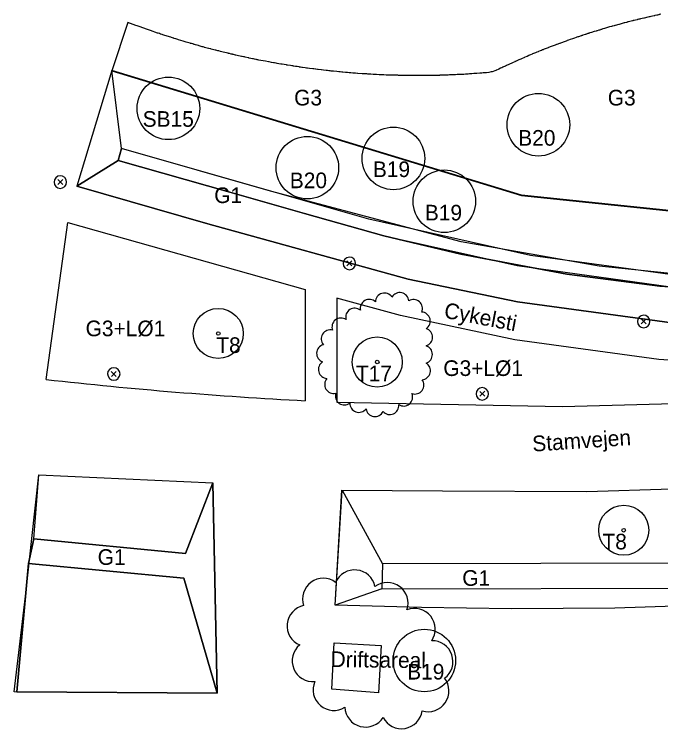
# Model space of a CAD drawing. Extents: x 0 to 512122, y 0 to 6212554.
# Drawn here: x 511513.3 to 511565, y 6211750.2 to 6211807.3 of the extents above; entities that cross this region are included whole.
import ezdxf

# ---------------------------------------------------------------- set-up
doc = ezdxf.new("R2010")
doc.units = 0
for name, color, linetype in [('_lights', 7, 'Continuous'), ('_LØ1', 7, 'Continuous'), ('Clouds', 7, 'Continuous'), ('L40 jord udlagt muld og grøft', 7, 'Continuous'), ('Pumpstation', 7, 'Continuous'), ('Skel', 7, 'Continuous'), ('TV_U_AFM_Symbl_Gul', 7, 'Continuous'), ('TV_U_LYS_Mastenummer', 7, 'Continuous')]:
    doc.layers.add(name, color=color, linetype=linetype)

# ---------------------------------------------------------------- blocks, each defined once
blk = doc.blocks.new('SOLITAIRE TREES')
at = {"layer": 'Skel'}
for radius in [2, 0.141]:
    blk.add_circle((0, 0), radius, dxfattribs=at)

msp = doc.modelspace()

# ---------------------------------------------------------------- linework, layer by layer
at = {"layer": '_lights'}
for p, q in [((511516.778, 6211794.103), (511517.172, 6211793.709)), ((511517.176, 6211794.107), (511516.782, 6211793.713)), ((511539.88, 6211787.6), (511540.274, 6211787.206)), ((511540.278, 6211787.604), (511539.884, 6211787.21)), ((511563.4, 6211782.962), (511563.795, 6211782.568)), ((511563.798, 6211782.966), (511563.404, 6211782.572)), ((511521.053, 6211778.766), (511521.447, 6211778.372)), ((511521.451, 6211778.77), (511521.057, 6211778.376)), ((511550.501, 6211777.177), (511550.895, 6211776.783)), ((511550.899, 6211777.181), (511550.505, 6211776.787))]:
    msp.add_line(p, q, dxfattribs=at)
for centre, start, end in [((511516.975, 6211793.906), 315.5636, 315), ((511516.975, 6211793.906), 315, 315.5636), ((511540.077, 6211787.403), 315.5636, 315), ((511540.077, 6211787.403), 315, 315.5636), ((511563.597, 6211782.765), 315.5636, 315), ((511563.597, 6211782.765), 315, 315.5636), ((511521.25, 6211778.569), 315.5636, 315), ((511521.25, 6211778.569), 315, 315.5636), ((511550.698, 6211776.98), 315.5636, 315), ((511550.698, 6211776.98), 315, 315.5636)]:
    msp.add_arc(centre, 0.5, start, end, dxfattribs=at)
at = {"layer": '_LØ1'}
msp.add_line((511515.849, 6211778.128), (511517.576, 6211790.672), dxfattribs=at)
msp.add_lwpolyline([(511517.576, 6211790.672), (511536.556, 6211785.33), (511536.556, 6211776.428)], dxfattribs=at)
msp.add_lwpolyline([(511539.066, 6211784.628), (511539.066, 6211776.31), (511557.102, 6211775.97), (511569.966, 6211776.326), (511576.1, 6211777.084), (511580.076, 6211777.733), (511581.646, 6211778.064), (511583.922, 6211778.583), (511584.736, 6211778.794), (511585.399, 6211778.957), (511578.113, 6211778.822), (511564.816, 6211779.711), (511553.308, 6211781.287), (511544.168, 6211783.234)], close=True, dxfattribs=at)
msp.add_arc((511554.612, 6212123.208), 347.25, 263.59085, 267.0195, dxfattribs=at)
at = {"layer": 'Clouds'}
for centre, radius, start, end in [((511542.881, 6211784.313), 0.72, 33.459, 178.459), ((511544.106, 6211784.352), 0.72, 5.2147, 150.2147), ((511541.668, 6211783.808), 0.72, 46.7383, 191.7383), ((511545.198, 6211783.803), 0.72, 336.3943, 121.3943), ((511540.504, 6211783.107), 0.72, 50.4047, 195.4047), ((511545.827, 6211782.796), 0.72, 302.5784, 87.5784), ((511539.405, 6211782.32), 0.72, 55.8288, 200.8288), ((511538.548, 6211781.368), 0.72, 75.1328, 220.1328), ((511545.998, 6211781.502), 0.72, 287.5, 72.5), ((511538.183, 6211780.208), 0.72, 104.9369, 249.9369), ((511545.997, 6211780.13), 0.72, 287.4096, 72.4096), ((511538.321, 6211778.924), 0.72, 122.3096, 267.3096), ((511545.84, 6211778.827), 0.72, 273.7995, 58.7995), ((511538.824, 6211777.725), 0.72, 138.2459, 283.2459), ((511545.309, 6211777.679), 0.72, 251.5756, 36.5756), ((511539.676, 6211776.81), 0.72, 162.6551, 307.6551), ((511544.415, 6211776.724), 0.72, 237.2694, 22.2694), ((511540.836, 6211776.216), 0.72, 178.0972, 323.0972), ((511543.31, 6211776.042), 0.72, 221.0491, 6.0491), ((511542.123, 6211775.89), 0.72, 188.5215, 333.5215), ((511540.499, 6211761.246), 1.658, 11.4218, 156.4218), ((511537.993, 6211760.576), 1.658, 53.5024, 198.5024), ((511543.11, 6211760.239), 1.659, 341.4203, 126.4203), ((511536.76, 6211758.427), 1.658, 101.8288, 246.8288), ((511545.279, 6211758.164), 1.659, 326.0856, 111.0856), ((511546.697, 6211755.579), 1.659, 306.4469, 91.4469), ((511537.17, 6211755.629), 1.659, 129.8492, 274.8492), ((511538.837, 6211753.328), 1.658, 156.995, 301.995), ((511546.376, 6211753.225), 1.658, 252.9674, 37.9674), ((511541.373, 6211751.996), 1.659, 182.559, 327.559), ((511544.247, 6211751.864), 1.658, 207.2264, 352.2264)]:
    msp.add_arc(centre, radius, start, end, dxfattribs=at)
at = {"layer": 'L40 jord udlagt muld og grøft'}
msp.add_line((511521.099, 6211802.832), (511518.303, 6211793.584), dxfattribs=at)
for points in [[(511564.982, 6211807.323), (511564.843, 6211807.293), (511564.828, 6211807.29), (511564.776, 6211807.279), (511564.703, 6211807.264), (511564.64, 6211807.25), (511564.485, 6211807.218), (511564.454, 6211807.211), (511564.446, 6211807.209), (511564.444, 6211807.209), (511564.167, 6211807.149), (511564.084, 6211807.13), (511564.048, 6211807.122), (511563.94, 6211807.099), (511563.923, 6211807.095), (511563.92, 6211807.094), (511563.625, 6211807.023), (511563.6, 6211807.017), (511563.49, 6211806.99), (511563.356, 6211806.958), (511563.343, 6211806.955), (511563.286, 6211806.941), (511563.259, 6211806.935), (511563.21, 6211806.923), (511563.14, 6211806.906), (511563.103, 6211806.897), (511563.083, 6211806.892), (511562.954, 6211806.861), (511562.837, 6211806.833), (511562.763, 6211806.815), (511562.75, 6211806.812), (511562.735, 6211806.808), (511562.733, 6211806.807), (511562.71, 6211806.802), (511562.502, 6211806.749), (511562.383, 6211806.719), (511562.332, 6211806.707), (511562.298, 6211806.698), (511562.269, 6211806.69), (511562.214, 6211806.675), (511562.102, 6211806.644), (511562.06, 6211806.633), (511562.046, 6211806.629), (511561.892, 6211806.587), (511561.889, 6211806.586), (511561.873, 6211806.582), (511561.872, 6211806.582), (511561.713, 6211806.538), (511561.648, 6211806.52), (511561.639, 6211806.518), (511561.61, 6211806.51), (511561.332, 6211806.435), (511561.29, 6211806.424), (511561.238, 6211806.41), (511561.087, 6211806.368), (511561.058, 6211806.36), (511561.028, 6211806.352), (511560.88, 6211806.312), (511560.863, 6211806.307), (511560.861, 6211806.307), (511560.778, 6211806.281), (511560.718, 6211806.263), (511560.466, 6211806.186), (511560.334, 6211806.147), (511560.226, 6211806.114), (511560.184, 6211806.101), (511560.155, 6211806.092), (511560.066, 6211806.065), (511560.027, 6211806.053), (511560.003, 6211806.046), (511559.891, 6211806.012), (511559.89, 6211806.012), (511559.843, 6211805.997), (511559.808, 6211805.987), (511559.651, 6211805.939), (511559.433, 6211805.873), (511559.308, 6211805.834), (511559.276, 6211805.824), (511559.268, 6211805.822), (511559.216, 6211805.805), (511559.187, 6211805.795), (511559.135, 6211805.777), (511559.021, 6211805.739), (511558.985, 6211805.727), (511558.952, 6211805.716), (511558.746, 6211805.647), (511558.743, 6211805.646), (511558.701, 6211805.632), (511558.661, 6211805.619), (511558.629, 6211805.608), (511558.605, 6211805.6), (511558.385, 6211805.526), (511558.365, 6211805.519), (511558.348, 6211805.514), (511558.259, 6211805.484), (511558.205, 6211805.466), (511558.081, 6211805.425), (511558.07, 6211805.421), (511558.058, 6211805.417), (511557.919, 6211805.37), (511557.721, 6211805.302), (511557.591, 6211805.255), (511557.485, 6211805.216), (511557.447, 6211805.203), (511557.446, 6211805.202), (511557.404, 6211805.187), (511557.155, 6211805.095), (511557.108, 6211805.078), (511556.945, 6211805.018), (511556.898, 6211805.001), (511556.868, 6211804.99), (511556.661, 6211804.914), (511556.641, 6211804.906), (511556.575, 6211804.882), (511556.512, 6211804.859), (511556.138, 6211804.718), (511556.113, 6211804.709), (511556.076, 6211804.694), (511556.002, 6211804.664), (511555.958, 6211804.647), (511555.793, 6211804.581), (511555.654, 6211804.525), (511555.605, 6211804.505), (511555.569, 6211804.491), (511555.523, 6211804.473), (511555.439, 6211804.439), (511555.315, 6211804.39), (511555.2, 6211804.344), (511555.165, 6211804.33), (511555.069, 6211804.291), (511555.054, 6211804.285), (511555.011, 6211804.268), (511554.945, 6211804.241), (511554.721, 6211804.152), (511554.688, 6211804.137), (511554.544, 6211804.075), (511554.477, 6211804.046), (511554.474, 6211804.045), (511554.431, 6211804.026), (511554.28, 6211803.961), (511554.114, 6211803.89), (511554.087, 6211803.878), (511554.069, 6211803.87), (511553.83, 6211803.766), (511553.786, 6211803.747), (511553.774, 6211803.742), (511553.701, 6211803.71), (511553.612, 6211803.672), (511553.355, 6211803.561), (511553.345, 6211803.556), (511553.311, 6211803.542), (511553.291, 6211803.533), (511553.156, 6211803.471), (511553.111, 6211803.45), (511552.813, 6211803.311), (511552.648, 6211803.234), (511552.545, 6211803.186), (511552.397, 6211803.117), (511552.343, 6211803.092), (511552.259, 6211803.053), (511552.154, 6211803.004), (511552.035, 6211802.948), (511551.979, 6211802.922), (511551.839, 6211802.857), (511551.839, 6211802.857), (511551.823, 6211802.85), (511551.814, 6211802.845), (511551.777, 6211802.831), (511551.496, 6211802.726), (511551.446, 6211802.716), (511551.419, 6211802.711), (511551.229, 6211802.674), (511551.229, 6211802.674), (511551.222, 6211802.673), (511551.041, 6211802.649), (511551.024, 6211802.647), (511550.911, 6211802.639), (511550.877, 6211802.637), (511550.839, 6211802.634), (511550.786, 6211802.63), (511550.781, 6211802.63), (511550.661, 6211802.622), (511550.601, 6211802.618), (511550.558, 6211802.615), (511550.504, 6211802.611), (511550.269, 6211802.594), (511550.161, 6211802.586), (511550.013, 6211802.576), (511549.854, 6211802.565), (511549.788, 6211802.56), (511549.728, 6211802.556), (511549.675, 6211802.553), (511549.579, 6211802.546), (511549.533, 6211802.543), (511549.466, 6211802.538), (511549.453, 6211802.537), (511549.369, 6211802.531), (511549.223, 6211802.521), (511549.112, 6211802.513), (511549.079, 6211802.511), (511549.06, 6211802.51), (511548.792, 6211802.5), (511548.789, 6211802.5), (511548.698, 6211802.496), (511548.555, 6211802.491), (511548.352, 6211802.483), (511548.245, 6211802.479), (511548.214, 6211802.478), (511548.192, 6211802.477), (511548.124, 6211802.475), (511548.084, 6211802.473), (511547.985, 6211802.469), (511547.94, 6211802.467), (511547.873, 6211802.465), (511547.821, 6211802.463), (511547.782, 6211802.461), (511547.675, 6211802.457), (511547.443, 6211802.448), (511547.312, 6211802.443), (511547.285, 6211802.442), (511547.236, 6211802.44), (511547.034, 6211802.434), (511547.004, 6211802.433), (511546.906, 6211802.431), (511546.776, 6211802.43), (511546.699, 6211802.43), (511546.645, 6211802.429), (511546.455, 6211802.428), (511546.442, 6211802.428), (511546.411, 6211802.428), (511546.375, 6211802.427), (511546.356, 6211802.427), (511546.295, 6211802.427), (511546.285, 6211802.427), (511546.006, 6211802.425), (511545.945, 6211802.425), (511545.78, 6211802.423), (511545.625, 6211802.422), (511545.564, 6211802.422), (511545.51, 6211802.422), (511545.475, 6211802.422), (511545.444, 6211802.422), (511545.366, 6211802.421), (511545.299, 6211802.42), (511544.997, 6211802.42), (511544.968, 6211802.42), (511544.783, 6211802.423), (511544.749, 6211802.424), (511544.611, 6211802.426), (511544.608, 6211802.426), (511544.515, 6211802.429), (511544.429, 6211802.431), (511544.369, 6211802.432), (511544.271, 6211802.434), (511544.053, 6211802.44), (511543.999, 6211802.442), (511543.951, 6211802.443), (511543.93, 6211802.443), (511543.742, 6211802.448), (511543.693, 6211802.449), (511543.683, 6211802.449), (511543.615, 6211802.451), (511543.582, 6211802.452), (511543.427, 6211802.456), (511543.238, 6211802.461), (511543.177, 6211802.462), (511543.027, 6211802.466), (511542.821, 6211802.473), (511542.661, 6211802.482), (511542.564, 6211802.488), (511542.561, 6211802.488), (511542.46, 6211802.494), (511542.237, 6211802.506), (511542.219, 6211802.507), (511542.212, 6211802.507), (511542.151, 6211802.511), (511542.07, 6211802.516), (511541.979, 6211802.521), (511541.806, 6211802.531), (511541.714, 6211802.536), (511541.546, 6211802.545), (511541.462, 6211802.55), (511541.237, 6211802.563), (511541.206, 6211802.565), (511541.111, 6211802.571), (511540.753, 6211802.592), (511540.724, 6211802.595), (511540.573, 6211802.608), (511540.536, 6211802.611), (511540.51, 6211802.614), (511540.478, 6211802.617), (511540.367, 6211802.626), (511540.199, 6211802.641), (511540.13, 6211802.647), (511540.07, 6211802.653), (511540.058, 6211802.654), (511539.929, 6211802.665), (511539.815, 6211802.675), (511539.773, 6211802.679), (511539.769, 6211802.679), (511539.543, 6211802.7), (511539.534, 6211802.7), (511539.474, 6211802.706), (511539.33, 6211802.719), (511539.306, 6211802.721), (511539.288, 6211802.723), (511539.225, 6211802.728), (511539.083, 6211802.74), (511538.813, 6211802.766), (511538.743, 6211802.773), (511538.62, 6211802.785), (511538.534, 6211802.796), (511538.44, 6211802.807), (511538.338, 6211802.819), (511538.218, 6211802.834), (511538.217, 6211802.834), (511538.214, 6211802.834), (511538.008, 6211802.86), (511537.852, 6211802.878), (511537.823, 6211802.882), (511537.593, 6211802.91), (511537.543, 6211802.916), (511537.405, 6211802.933), (511537.363, 6211802.938), (511537.227, 6211802.954), (511537.155, 6211802.963), (511536.893, 6211802.995), (511536.741, 6211803.013), (511536.683, 6211803.02), (511536.676, 6211803.021), (511536.654, 6211803.024), (511536.554, 6211803.039), (511536.339, 6211803.072), (511536.284, 6211803.081), (511536.17, 6211803.098), (511536.156, 6211803.1), (511536.102, 6211803.108), (511536.053, 6211803.116), (511535.916, 6211803.138), (511535.762, 6211803.161), (511535.613, 6211803.184), (511535.574, 6211803.19), (511535.517, 6211803.199), (511535.468, 6211803.206), (511535.372, 6211803.221), (511535.143, 6211803.256), (511535.079, 6211803.266), (511535.061, 6211803.269), (511535.015, 6211803.276), (511534.871, 6211803.298), (511534.709, 6211803.323), (511534.599, 6211803.34), (511534.595, 6211803.341), (511534.435, 6211803.37), (511534.3, 6211803.395), (511534.237, 6211803.407), (511534.105, 6211803.432), (511534.096, 6211803.434), (511534.029, 6211803.447), (511534.027, 6211803.447), (511533.852, 6211803.48), (511533.668, 6211803.513), (511533.648, 6211803.517), (511533.626, 6211803.521), (511533.386, 6211803.566), (511533.188, 6211803.603), (511533.006, 6211803.637), (511532.853, 6211803.665), (511532.77, 6211803.681), (511532.726, 6211803.689), (511532.72, 6211803.69), (511532.658, 6211803.702), (511532.598, 6211803.714), (511532.486, 6211803.737), (511532.414, 6211803.753), (511532.344, 6211803.768), (511532.073, 6211803.827), (511532.04, 6211803.834), (511531.991, 6211803.845), (511531.984, 6211803.847), (511531.75, 6211803.899), (511531.698, 6211803.91), (511531.628, 6211803.925), (511531.604, 6211803.93), (511531.522, 6211803.948), (511531.501, 6211803.953), (511531.466, 6211803.96), (511531.119, 6211804.037), (511530.994, 6211804.064), (511530.989, 6211804.065), (511530.986, 6211804.066), (511530.812, 6211804.104), (511530.803, 6211804.106), (511530.741, 6211804.12), (511530.725, 6211804.124), (511530.682, 6211804.134), (511530.628, 6211804.146), (511530.495, 6211804.177), (511530.433, 6211804.192), (511530.406, 6211804.198), (511530.401, 6211804.199), (511530.386, 6211804.203), (511529.988, 6211804.303), (511529.791, 6211804.353), (511529.649, 6211804.389), (511529.572, 6211804.409), (511529.412, 6211804.449), (511529.412, 6211804.449), (511529.345, 6211804.466), (511529.24, 6211804.493), (511529.025, 6211804.547), (511529.008, 6211804.551), (511528.999, 6211804.554), (511528.844, 6211804.593), (511528.825, 6211804.598), (511528.618, 6211804.65), (511528.504, 6211804.68), (511528.481, 6211804.687), (511528.385, 6211804.714), (511528.352, 6211804.724), (511528.319, 6211804.734), (511528.078, 6211804.803), (511528.018, 6211804.82), (511527.907, 6211804.852), (511527.904, 6211804.852), (511527.877, 6211804.86), (511527.791, 6211804.884), (511527.694, 6211804.912), (511527.68, 6211804.916), (511527.66, 6211804.922), (511527.639, 6211804.928), (511527.62, 6211804.934), (511527.569, 6211804.948), (511527.46, 6211804.98), (511527.386, 6211805.001), (511527.356, 6211805.01), (511527.044, 6211805.099), (511526.967, 6211805.121), (511526.794, 6211805.172), (511526.424, 6211805.281), (511526.372, 6211805.298), (511526.361, 6211805.301), (511526.197, 6211805.354), (511526.078, 6211805.393), (511526.061, 6211805.398), (511526.045, 6211805.403), (511526.036, 6211805.406), (511525.929, 6211805.441), (511525.873, 6211805.459), (511525.803, 6211805.482), (511525.71, 6211805.511), (511525.258, 6211805.657), (511525.167, 6211805.686), (511525.118, 6211805.701), (511525.11, 6211805.704), (511524.977, 6211805.747), (511524.895, 6211805.774), (511524.803, 6211805.803), (511524.79, 6211805.807), (511524.776, 6211805.812), (511524.751, 6211805.82), (511524.188, 6211806.015), (511523.952, 6211806.099), (511523.272, 6211806.342), (511523.13, 6211806.393), (511523.01, 6211806.435), (511522.359, 6211806.678), (511521.1, 6211802.804)], [(511587.661, 6211789.352), (511553.83, 6211792.863), (511521.099, 6211802.832)], [(511521.1, 6211802.804), (511553.832, 6211792.835), (511587.663, 6211789.324)], [(511518.303, 6211793.584), (511528.762, 6211790.58), (511544.764, 6211786.14), (511553.526, 6211784.336), (511568.012, 6211782.359), (511577.451, 6211781.89), (511587.592, 6211782.058), (511584.385, 6211784.881), (511575.845, 6211784.871), (511564.889, 6211785.591), (511557.457, 6211786.555), (511548.985, 6211788.133), (511542.834, 6211789.608), (511536.487, 6211791.386), (511530.522, 6211793.089), (511521.61, 6211795.629), (511518.303, 6211793.584)], [(511600.554, 6211771.296), (511598.553, 6211771.04), (511599.609, 6211762.58), (511587.737, 6211761.296), (511572.192, 6211760.209), (511571.76, 6211768.724), (511569.762, 6211768.633), (511570.165, 6211760.136), (511561.305, 6211759.845), (511553.031, 6211759.792), (511545.838, 6211759.899), (511538.939, 6211760.077), (511539.481, 6211769.281), (511547.52, 6211769.212), (511559.062, 6211769.169), (511572.635, 6211769.6), (511585.486, 6211770.489), (511596.03, 6211771.388), (511605.924, 6211772.694)], [(511514.85, 6211765.386), (511526.975, 6211764.218), (511529.157, 6211769.854)], [(511539.489, 6211769.289), (511542.729, 6211763.379), (511542.663, 6211761.38), (511538.939, 6211760.073), (511539.489, 6211769.289)]]:
    msp.add_lwpolyline(points, dxfattribs=at)
for points in [[(511518.303, 6211793.584), (511521.61, 6211795.629), (511521.868, 6211796.58), (511521.099, 6211802.832)], [(511521.099, 6211802.832), (511553.83, 6211792.863), (511587.661, 6211789.352), (511584.588, 6211785.886), (511575.919, 6211785.865), (511566.312, 6211786.447), (511554.552, 6211788.039), (511541.642, 6211790.936), (511521.868, 6211796.58)], [(511521.868, 6211796.58), (511521.61, 6211795.629), (511542.847, 6211789.604), (511553.476, 6211787.233), (511566.734, 6211785.412), (511584.385, 6211784.881), (511584.587, 6211785.886), (511579.854, 6211785.81), (511570.145, 6211786.138), (511560.037, 6211787.174), (511549.002, 6211789.133), (511533.785, 6211793.174)], [(511521.61, 6211795.629), (511530.522, 6211793.089), (511536.487, 6211791.386), (511542.834, 6211789.608), (511548.985, 6211788.133), (511557.457, 6211786.555), (511564.889, 6211785.591), (511575.845, 6211784.871), (511584.385, 6211784.881), (511587.592, 6211782.058), (511577.451, 6211781.89), (511568.012, 6211782.359), (511553.526, 6211784.336), (511544.764, 6211786.14), (511528.762, 6211790.58), (511518.303, 6211793.584)], [(511514.697, 6211765.403), (511515.263, 6211770.498), (511529.157, 6211769.854), (511529.504, 6211753.047), (511513.298, 6211753.146), (511514.245, 6211761.262)], [(511529.504, 6211753.047), (511513.49, 6211753.143), (511514.445, 6211763.418), (511514.85, 6211765.386), (511515.263, 6211770.498), (511529.157, 6211769.854)], [(511529.157, 6211769.854), (511526.975, 6211764.218), (511514.85, 6211765.386), (511514.445, 6211763.418), (511526.856, 6211762.249), (511529.504, 6211753.047)], [(511526.975, 6211764.218), (511514.85, 6211765.386), (511514.445, 6211763.418), (511526.856, 6211762.249), (511529.504, 6211753.047), (511529.157, 6211769.854)], [(511539.489, 6211769.289), (511542.729, 6211763.379), (511542.663, 6211761.38), (511538.939, 6211760.073)], [(511529.504, 6211753.047), (511526.856, 6211762.249), (511514.445, 6211763.418), (511513.49, 6211753.143)], [(511542.729, 6211763.379), (511542.663, 6211761.38), (511568.125, 6211761.436), (511568.023, 6211763.433)]]:
    msp.add_lwpolyline(points, close=True, dxfattribs=at)
at = {"layer": 'Pumpstation'}
msp.add_lwpolyline([(511538.86, 6211757.068), (511542.623, 6211756.849), (511542.404, 6211753.086), (511538.668, 6211753.357), (511538.86, 6211757.068)], dxfattribs=at)
at = {"layer": 'TV_U_LYS_Mastenummer'}
for centre in [(511525.615, 6211799.8), (511525.615, 6211799.8), (511555.188, 6211798.491), (511555.188, 6211798.491), (511543.598, 6211795.8), (511543.598, 6211795.8), (511536.721, 6211795.063), (511536.721, 6211795.063), (511547.668, 6211792.376), (511547.668, 6211792.376), (511546.068, 6211755.658), (511546.068, 6211755.658)]:
    msp.add_circle(centre, 2.5, dxfattribs=at)

# ---------------------------------------------------------------- block references
at = {"layer": 'Skel'}
for p in [(511529.601, 6211781.806), (511542.305, 6211779.523), (511562.004, 6211766.074)]:
    msp.add_blockref('SOLITAIRE TREES', p, dxfattribs=at)

# ---------------------------------------------------------------- texts
at = {"layer": 'TV_U_AFM_Symbl_Gul'}
for s, p in [('G3', (511535.662, 6211800.033)), ('G3', (511560.731, 6211800.033)), ('SB15', (511523.558, 6211798.33)), ('B20', (511553.573, 6211796.819)), ('B19', (511541.956, 6211794.309)), ('B20', (511535.317, 6211793.42)), ('G1', (511529.276, 6211792.231)), ('B19', (511546.111, 6211790.842)), ('G3+LØ1', (511518.998, 6211781.585)), ('T8', (511529.443, 6211780.246)), ('G3+LØ1', (511547.586, 6211778.407)), ('T17', (511540.602, 6211777.988)), ('T8', (511560.302, 6211764.539)), ('G1', (511519.961, 6211763.305)), ('G1', (511549.1, 6211761.63)), ('B19', (511544.697, 6211754.14))]:
    msp.add_text(s, height=1.25, dxfattribs=at).set_placement(p)
for s, rotation, p in [('Cykelsti', 349.1497, (511547.576, 6211783.075)), ('Stamvejen', 3.8017, (511554.738, 6211772.359)), ('Driftsareal', 359.2457, (511538.571, 6211755.142))]:
    msp.add_text(s, height=1.25, rotation=rotation, dxfattribs=at).set_placement(p)

doc.saveas('drawing.dxf')
